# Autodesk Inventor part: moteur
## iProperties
Shininess: 64.0
Length Units: 11269
Angle Units: 11279
Time Units: 11290
Mass Units: 11283
Length Display Precision: 3
Angle Display Precision: 2
Compacted: True
Part Number: moteur
Document SubType Name: Modeling
Created: 2004-09
Material: Par défaut
Designer: Laurent
Density: 1 g/cm^3
Density: 0.0
Volumn: 0.0
Area: 0.0
PropertySet Name: Model Information
Control State: 0
Master: False
Checked Out: False
Author: Laurent
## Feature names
1. Extrusion1
2. Extrusion2
3. Extrusion5
4. Extrusion8
5. Extrusion11
6. Congé1 [Fillet]
7. Extrusion12
